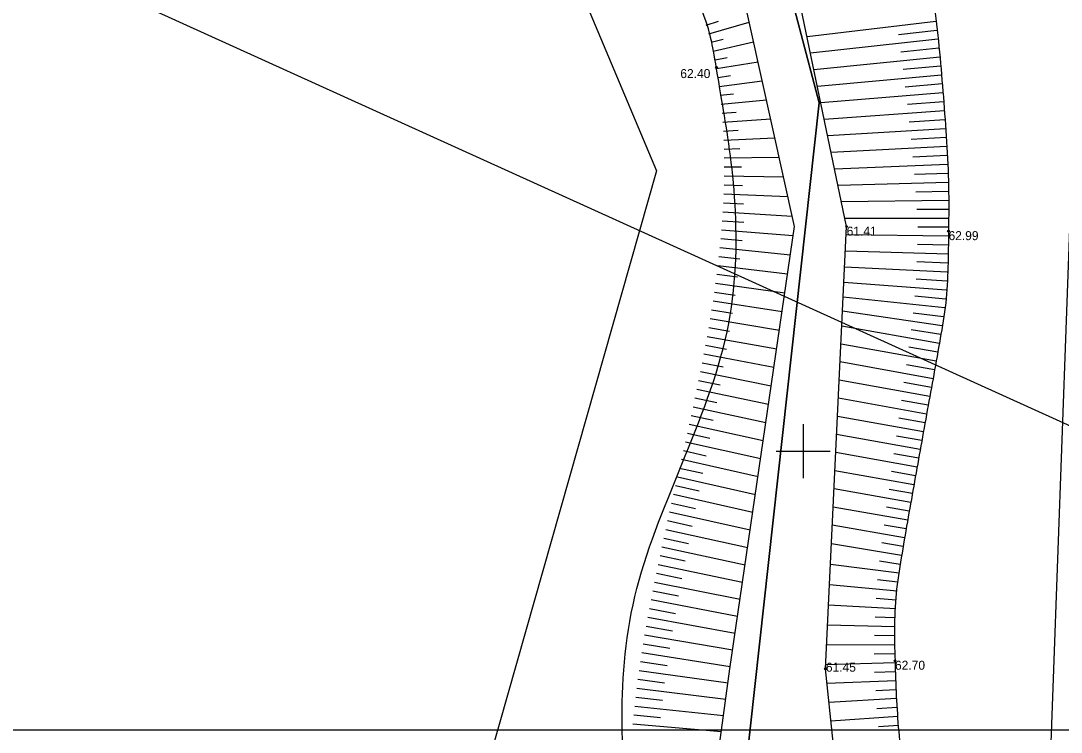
# Model space of a CAD drawing. Extents: x 616607 to 617499, y 408385 to 409695.
# Drawn here: x 617156.4 to 617214.4, y 409084.3 to 409124 of the extents above; entities that cross this region are included whole.
import ezdxf

# ---------------------------------------------------------------- set-up
doc = ezdxf.new("R2010")
doc.units = 0
for name, color, linetype in [('GEOD_ELEM_####_####_#', 7, 'Continuous'), ('HIDG_GRAV_####_####_#', 7, 'Continuous'), ('RAMI_PLAN_####_TKST_#', 7, 'Continuous'), ('RAMI_UZMR_####_####_#', 7, 'Continuous'), ('RELJ_AATZ_####_TKST_#', 7, 'Continuous'), ('RELJ_ELEM_####_####_#', 7, 'Continuous'), ('RELJ_NOGA_####_####_#', 7, 'Continuous'), ('ROBZ_IERR_####_####_#', 7, 'Continuous'), ('ROBZ_UZMR_####_####_#', 7, 'Continuous')]:
    doc.layers.add(name, color=color, linetype=linetype)

# ---------------------------------------------------------------- blocks, each defined once
blk = doc.blocks.new('PKT')
at = {"layer": 'RELJ_ELEM_####_####_#'}
blk.add_circle((0, 0), 0.05, dxfattribs=at)
blk = doc.blocks.new('KRUSTS')
at = {"layer": 'GEOD_ELEM_####_####_#'}
for p, q in [((0, 1.5), (0, 0)), ((-1.5, 0), (0, 0)), ((0, 0), (0, -1.5)), ((0, 0), (1.5, 0))]:
    blk.add_line(p, q, dxfattribs=at)

msp = doc.modelspace()

# ---------------------------------------------------------------- linework, layer by layer
at = {"layer": 'HIDG_GRAV_####_####_#'}
for points in [[(617196.049, 409072.553), (617193.886, 409072.979), (617195.921, 409087.874), (617195.921, 409087.874), (617199.518, 409112.516), (617194.569, 409134.842), (617162.019, 409207.474), (617151.93, 409229.107), (617149.428, 409241.28), (617152.359, 409253.938), (617188.564, 409303.055), (617197.968, 409312.659), (617223.456, 409346.169), (617232.567, 409363.51), (617247.671, 409422.509), (617276.576, 409461.456), (617285.007, 409472.526), (617327.765, 409527.3)], [(617198.671, 409072.074), (617200.929, 409072.435), (617202.532, 409075.622), (617201.237, 409087.874), (617202.422, 409112.516), (617197.415, 409136.544), (617162.613, 409207.758), (617153.021, 409229.447), (617150.525, 409241.262), (617153.298, 409253.658), (617189.431, 409302.264), (617198.754, 409312.12), (617224.478, 409345.652), (617234.105, 409363.027), (617250.009, 409421.44), (617285.914, 409471.848), (617328.6, 409526.531)]]:
    msp.add_lwpolyline(points, dxfattribs=at)
at = {"layer": 'RAMI_PLAN_####_TKST_#'}
msp.add_line((617156.405, 409127.944), (617287, 409068.676), dxfattribs=at)
msp.add_lwpolyline([(617109.674, 409084.461), (617109.674, 409290.339), (617251.246, 409290.339), (617251.246, 409084.461), (617109.674, 409084.461)], dxfattribs=at)
at = {"layer": 'RAMI_UZMR_####_####_#'}
msp.add_lwpolyline([(617101.571, 408748.246), (617213.472, 409074.039), (617215.883, 409140.56), (617165.121, 409241.478), (617252.137, 409353.424), (617269.572, 409425.099), (617332.631, 409510.312), (617439.945, 409622.037), (617425.373, 409635.959), (617242.079, 409440.82), (617216.614, 409355.716), (617136.613, 409246.751), (617191.828, 409115.62), (617145.545, 408952.8)], dxfattribs=at)
at = {"layer": 'RELJ_NOGA_####_####_#'}
for p, q in [((617194.588, 409123.746), (617195.272, 409123.966)), ((617194.588, 409123.746), (617194.588, 409123.746)), ((617194.734, 409123.268), (617196.991, 409123.918)), ((617207.391, 409123.949), (617200.219, 409123.088)), ((617207.391, 409123.949), (617207.392, 409123.949)), ((617194.734, 409123.268), (617194.733, 409123.268)), ((617207.45, 409123.452), (617205.309, 409123.207)), ((617207.45, 409123.452), (617207.45, 409123.452)), ((617194.866, 409122.786), (617195.54, 409122.958)), ((617194.866, 409122.786), (617194.866, 409122.786)), ((617194.984, 409122.3), (617197.235, 409122.813)), ((617207.506, 409122.955), (617200.409, 409122.173)), ((617207.506, 409122.955), (617207.507, 409122.956)), ((617194.984, 409122.3), (617194.983, 409122.3)), ((617195.088, 409121.811), (617195.77, 409121.943)), ((617207.61, 409121.961), (617200.6, 409121.257)), ((617207.559, 409122.458), (617205.442, 409122.239)), ((617207.559, 409122.458), (617207.559, 409122.458)), ((617207.61, 409121.961), (617207.611, 409121.961)), ((617195.088, 409121.811), (617195.088, 409121.811)), ((617195.176, 409121.319), (617197.483, 409121.696)), ((617207.658, 409121.463), (617205.57, 409121.264)), ((617207.658, 409121.463), (617207.659, 409121.463)), ((617195.176, 409121.319), (617195.175, 409121.319)), ((617195.253, 409120.825), (617195.957, 409120.928)), ((617195.253, 409120.825), (617195.253, 409120.825)), ((617207.705, 409120.965), (617200.794, 409120.329)), ((617207.705, 409120.965), (617207.706, 409120.966)), ((617195.322, 409120.33), (617195.321, 409120.329)), ((617195.322, 409120.33), (617197.716, 409120.643)), ((617207.748, 409120.467), (617205.69, 409120.29)), ((617207.748, 409120.467), (617207.749, 409120.467)), ((617195.383, 409119.833), (617196.119, 409119.917)), ((617195.383, 409119.833), (617195.383, 409119.833)), ((617195.437, 409119.336), (617197.95, 409119.59)), ((617207.79, 409119.969), (617200.983, 409119.421)), ((617207.79, 409119.969), (617207.791, 409119.969)), ((617195.437, 409119.336), (617195.436, 409119.336)), ((617207.829, 409119.471), (617205.804, 409119.317)), ((617207.829, 409119.471), (617207.83, 409119.471)), ((617195.482, 409118.838), (617196.258, 409118.902)), ((617195.482, 409118.838), (617195.482, 409118.838)), ((617195.52, 409118.34), (617198.188, 409118.516)), ((617207.866, 409118.972), (617201.177, 409118.489)), ((617207.901, 409118.473), (617205.914, 409118.335)), ((617207.866, 409118.972), (617207.867, 409118.972)), ((617207.901, 409118.473), (617207.902, 409118.473)), ((617195.52, 409118.34), (617195.519, 409118.34)), ((617195.551, 409117.841), (617196.377, 409117.885)), ((617207.934, 409117.974), (617201.369, 409117.569)), ((617207.934, 409117.974), (617207.935, 409117.974)), ((617195.551, 409117.841), (617195.551, 409117.841)), ((617195.575, 409117.341), (617195.574, 409117.341)), ((617195.575, 409117.341), (617198.422, 409117.459)), ((617207.964, 409117.475), (617206.015, 409117.362)), ((617207.964, 409117.475), (617207.964, 409117.475)), ((617195.591, 409116.841), (617196.476, 409116.865)), ((617195.591, 409116.841), (617195.591, 409116.841)), ((617207.992, 409116.976), (617201.561, 409116.646)), ((617207.992, 409116.976), (617207.993, 409116.976)), ((617195.601, 409116.342), (617195.6, 409116.342)), ((617195.601, 409116.342), (617198.66, 409116.384)), ((617208.016, 409116.477), (617206.109, 409116.385)), ((617208.016, 409116.477), (617208.017, 409116.477)), ((617195.603, 409115.842), (617195.603, 409115.842)), ((617195.603, 409115.842), (617196.556, 409115.842)), ((617208.038, 409115.977), (617201.755, 409115.714)), ((617208.038, 409115.977), (617208.039, 409115.977)), ((617195.6, 409115.342), (617195.599, 409115.342)), ((617195.6, 409115.342), (617198.901, 409115.297)), ((617208.073, 409114.978), (617201.945, 409114.802)), ((617208.057, 409115.477), (617206.194, 409115.415)), ((617208.057, 409115.477), (617208.057, 409115.477)), ((617208.073, 409114.978), (617208.074, 409114.978)), ((617195.59, 409114.842), (617195.589, 409114.842)), ((617195.59, 409114.842), (617196.62, 409114.813)), ((617208.085, 409114.478), (617206.271, 409114.44)), ((617208.085, 409114.478), (617208.085, 409114.478)), ((617195.552, 409113.842), (617195.551, 409113.842)), ((617195.552, 409113.842), (617196.665, 409113.787)), ((617195.574, 409114.342), (617195.573, 409114.342)), ((617195.574, 409114.342), (617199.144, 409114.203)), ((617208.094, 409113.978), (617202.134, 409113.895)), ((617208.094, 409113.978), (617208.095, 409113.978)), ((617195.524, 409113.343), (617195.523, 409113.343)), ((617195.524, 409113.343), (617199.386, 409113.108)), ((617208.1, 409113.478), (617206.339, 409113.463)), ((617208.1, 409113.478), (617208.1, 409113.478)), ((617195.491, 409112.844), (617195.49, 409112.844)), ((617195.491, 409112.844), (617196.696, 409112.757)), ((617208.101, 409112.978), (617202.326, 409112.973)), ((617208.101, 409112.978), (617208.102, 409112.978)), ((617195.452, 409112.346), (617195.451, 409112.346)), ((617195.452, 409112.346), (617199.445, 409112.016)), ((617208.094, 409111.978), (617202.4, 409112.063)), ((617208.099, 409112.478), (617206.395, 409112.494)), ((617208.099, 409112.478), (617208.1, 409112.478)), ((617195.408, 409111.848), (617195.408, 409111.848)), ((617195.408, 409111.848), (617196.596, 409111.739)), ((617208.084, 409111.478), (617206.372, 409111.516)), ((617208.084, 409111.478), (617208.085, 409111.478)), ((617208.094, 409111.978), (617208.095, 409111.978)), ((617195.36, 409111.35), (617195.359, 409111.35)), ((617195.36, 409111.35), (617199.288, 409110.943)), ((617208.071, 409110.978), (617202.356, 409111.151)), ((617208.071, 409110.978), (617208.072, 409110.978)), ((617195.249, 409110.356), (617195.248, 409110.356)), ((617195.249, 409110.356), (617199.133, 409109.882)), ((617195.306, 409110.853), (617195.306, 409110.853)), ((617195.306, 409110.853), (617196.478, 409110.721)), ((617208.054, 409110.479), (617206.338, 409110.552)), ((617208.054, 409110.479), (617208.054, 409110.479)), ((617195.186, 409109.86), (617195.186, 409109.86)), ((617195.186, 409109.86), (617196.348, 409109.711)), ((617208.031, 409109.979), (617202.313, 409110.255)), ((617208.031, 409109.979), (617208.032, 409109.979)), ((617195.12, 409109.365), (617195.119, 409109.365)), ((617195.12, 409109.365), (617198.98, 409108.834)), ((617207.967, 409108.981), (617202.272, 409109.41)), ((617208.002, 409109.48), (617206.29, 409109.591)), ((617208.002, 409109.48), (617208.003, 409109.48)), ((617195.05, 409108.87), (617195.05, 409108.87)), ((617195.05, 409108.87), (617196.206, 409108.7)), ((617207.875, 409107.985), (617202.233, 409108.589)), ((617207.925, 409108.483), (617206.223, 409108.636)), ((617207.967, 409108.981), (617207.968, 409108.981)), ((617194.976, 409108.375), (617194.975, 409108.375)), ((617194.976, 409108.375), (617198.827, 409107.786)), ((617207.925, 409108.483), (617207.926, 409108.483)), ((617194.899, 409107.881), (617194.898, 409107.881)), ((617194.899, 409107.881), (617196.054, 409107.697)), ((617207.749, 409106.993), (617202.196, 409107.814)), ((617207.817, 409107.489), (617206.136, 409107.701)), ((617207.817, 409107.489), (617207.817, 409107.489)), ((617207.875, 409107.985), (617207.876, 409107.985)), ((617194.734, 409106.895), (617194.733, 409106.895)), ((617194.734, 409106.895), (617195.893, 409106.693)), ((617194.818, 409107.388), (617194.817, 409107.388)), ((617194.818, 409107.388), (617198.675, 409106.74)), ((617207.587, 409106.007), (617202.155, 409106.967)), ((617207.749, 409106.993), (617207.75, 409106.993)), ((617194.647, 409106.402), (617194.646, 409106.403)), ((617194.647, 409106.402), (617198.524, 409105.707)), ((617207.672, 409106.499), (617206.024, 409106.772)), ((617207.672, 409106.499), (617207.673, 409106.499)), ((617194.557, 409105.911), (617194.557, 409105.911)), ((617194.557, 409105.911), (617195.724, 409105.695)), ((617207.411, 409105.022), (617202.107, 409105.975)), ((617207.499, 409105.515), (617205.889, 409105.802)), ((617207.587, 409106.007), (617207.588, 409106.007)), ((617194.465, 409105.419), (617194.464, 409105.419)), ((617194.465, 409105.419), (617198.373, 409104.676)), ((617207.499, 409105.515), (617207.499, 409105.514)), ((617194.37, 409104.928), (617194.37, 409104.928)), ((617194.37, 409104.928), (617195.548, 409104.698)), ((617207.234, 409104.038), (617202.059, 409104.974)), ((617207.323, 409104.53), (617205.751, 409104.815)), ((617207.323, 409104.53), (617207.323, 409104.53)), ((617207.411, 409105.022), (617207.412, 409105.022)), ((617194.174, 409103.948), (617194.174, 409103.948)), ((617194.174, 409103.948), (617195.366, 409103.703)), ((617194.273, 409104.438), (617194.272, 409104.438)), ((617194.273, 409104.438), (617198.223, 409103.647)), ((617207.055, 409103.054), (617202.011, 409103.969)), ((617207.234, 409104.038), (617207.235, 409104.038)), ((617194.073, 409103.458), (617194.072, 409103.458)), ((617194.073, 409103.458), (617198.075, 409102.63)), ((617207.145, 409103.546), (617205.612, 409103.824)), ((617207.145, 409103.546), (617207.145, 409103.546)), ((617193.97, 409102.969), (617193.97, 409102.969)), ((617193.97, 409102.969), (617195.179, 409102.713)), ((617206.877, 409102.07), (617201.962, 409102.962)), ((617206.966, 409102.562), (617205.472, 409102.833)), ((617207.055, 409103.054), (617207.056, 409103.054)), ((617193.866, 409102.48), (617193.865, 409102.48)), ((617193.866, 409102.48), (617197.925, 409101.607)), ((617206.966, 409102.562), (617206.966, 409102.562)), ((617193.761, 409101.991), (617193.76, 409101.991)), ((617193.761, 409101.991), (617194.988, 409101.725)), ((617206.699, 409101.086), (617201.913, 409101.943)), ((617206.788, 409101.578), (617205.333, 409101.841)), ((617206.877, 409102.07), (617206.878, 409102.07)), ((617193.654, 409101.502), (617193.653, 409101.503)), ((617193.654, 409101.502), (617197.778, 409100.596)), ((617206.699, 409101.086), (617206.7, 409101.086)), ((617206.788, 409101.578), (617206.788, 409101.578)), ((617193.437, 409100.526), (617193.436, 409100.526)), ((617193.437, 409100.526), (617197.631, 409099.588)), ((617193.546, 409101.014), (617193.546, 409101.014)), ((617193.546, 409101.014), (617194.793, 409100.737)), ((617206.523, 409100.102), (617201.865, 409100.932)), ((617206.611, 409100.594), (617205.194, 409100.848)), ((617206.611, 409100.594), (617206.611, 409100.594)), ((617193.328, 409100.038), (617193.328, 409100.038)), ((617193.328, 409100.038), (617194.597, 409099.752)), ((617206.348, 409099.117), (617201.816, 409099.924)), ((617206.523, 409100.102), (617206.524, 409100.102)), ((617193.218, 409099.55), (617193.217, 409099.551)), ((617193.218, 409099.55), (617197.485, 409098.589)), ((617206.435, 409099.61), (617205.057, 409099.855)), ((617206.435, 409099.61), (617206.436, 409099.61)), ((617193.108, 409099.063), (617193.108, 409099.063)), ((617193.108, 409099.063), (617194.399, 409098.77)), ((617206.173, 409098.133), (617201.768, 409098.915)), ((617206.26, 409098.625), (617204.92, 409098.863)), ((617206.348, 409099.117), (617206.349, 409099.117)), ((617192.998, 409098.575), (617192.997, 409098.575)), ((617192.998, 409098.575), (617197.339, 409097.592)), ((617206.26, 409098.625), (617206.26, 409098.625)), ((617192.777, 409097.6), (617192.776, 409097.6)), ((617192.777, 409097.6), (617197.195, 409096.602)), ((617192.887, 409098.087), (617192.887, 409098.087)), ((617192.887, 409098.087), (617194.201, 409097.79)), ((617205.998, 409097.148), (617201.719, 409097.904)), ((617206.085, 409097.64), (617204.783, 409097.871)), ((617206.085, 409097.64), (617206.086, 409097.64)), ((617206.173, 409098.133), (617206.174, 409098.133)), ((617192.667, 409097.112), (617192.667, 409097.112)), ((617192.667, 409097.112), (617194.004, 409096.812)), ((617205.998, 409097.148), (617205.999, 409097.148)), ((617192.557, 409096.624), (617192.556, 409096.624)), ((617192.557, 409096.624), (617197.051, 409095.616)), ((617205.825, 409096.163), (617201.67, 409096.889)), ((617205.912, 409096.656), (617204.647, 409096.878)), ((617205.912, 409096.656), (617205.912, 409096.656)), ((617192.448, 409096.136), (617192.448, 409096.136)), ((617192.448, 409096.136), (617193.808, 409095.834)), ((617205.654, 409095.178), (617201.622, 409095.876)), ((617205.739, 409095.671), (617204.511, 409095.884)), ((617205.825, 409096.163), (617205.826, 409096.163)), ((617192.34, 409095.648), (617192.339, 409095.648)), ((617192.34, 409095.648), (617196.908, 409094.638)), ((617205.739, 409095.671), (617205.74, 409095.671)), ((617192.127, 409094.671), (617192.126, 409094.671)), ((617192.127, 409094.671), (617196.767, 409093.674)), ((617192.233, 409095.16), (617192.233, 409095.16)), ((617192.233, 409095.16), (617193.614, 409094.857)), ((617205.485, 409094.192), (617201.572, 409094.846)), ((617205.569, 409094.685), (617204.377, 409094.889)), ((617205.569, 409094.685), (617205.569, 409094.685)), ((617205.654, 409095.178), (617205.655, 409095.178)), ((617192.022, 409094.182), (617192.022, 409094.182)), ((617192.022, 409094.182), (617193.425, 409093.885)), ((617205.485, 409094.192), (617205.486, 409094.192)), ((617191.919, 409093.693), (617191.918, 409093.693)), ((617191.919, 409093.693), (617196.626, 409092.708)), ((617205.34, 409093.203), (617201.517, 409093.692)), ((617205.408, 409093.698), (617204.249, 409093.868)), ((617205.408, 409093.698), (617205.408, 409093.698)), ((617191.817, 409093.203), (617191.817, 409093.203)), ((617191.817, 409093.203), (617193.239, 409092.911)), ((617205.34, 409093.203), (617205.341, 409093.203)), ((617191.717, 409092.713), (617191.716, 409092.714)), ((617191.717, 409092.713), (617196.487, 409091.754)), ((617205.23, 409092.209), (617201.462, 409092.559)), ((617205.281, 409092.707), (617204.143, 409092.834)), ((617205.281, 409092.707), (617205.281, 409092.706)), ((617191.619, 409092.223), (617191.619, 409092.223)), ((617191.619, 409092.223), (617193.059, 409091.939)), ((617205.189, 409091.711), (617204.063, 409091.797)), ((617205.23, 409092.209), (617205.231, 409092.209)), ((617191.43, 409091.241), (617191.43, 409091.241)), ((617191.43, 409091.241), (617192.885, 409090.968)), ((617191.524, 409091.732), (617191.523, 409091.732)), ((617191.524, 409091.732), (617196.348, 409090.803)), ((617205.156, 409091.212), (617201.408, 409091.43)), ((617205.156, 409091.212), (617205.157, 409091.212)), ((617205.189, 409091.711), (617205.189, 409091.711)), ((617191.339, 409090.749), (617191.338, 409090.75)), ((617191.339, 409090.749), (617196.211, 409089.861)), ((617205.131, 409090.713), (617204.006, 409090.76)), ((617205.131, 409090.713), (617205.131, 409090.713)), ((617191.251, 409090.257), (617191.251, 409090.257)), ((617191.251, 409090.257), (617192.719, 409089.998)), ((617205.113, 409090.213), (617201.354, 409090.306)), ((617205.113, 409090.213), (617205.114, 409090.213)), ((617191.166, 409089.765), (617191.165, 409089.765)), ((617191.166, 409089.765), (617196.075, 409088.928)), ((617205.104, 409089.713), (617203.971, 409089.728)), ((617205.104, 409089.713), (617205.104, 409089.713)), ((617191.084, 409089.271), (617191.084, 409089.271)), ((617191.084, 409089.271), (617192.561, 409089.029)), ((617205.102, 409089.213), (617201.3, 409089.19)), ((617205.102, 409089.213), (617205.103, 409089.213)), ((617190.93, 409088.283), (617190.929, 409088.283)), ((617190.93, 409088.283), (617192.414, 409088.062)), ((617191.005, 409088.778), (617191.004, 409088.778)), ((617191.005, 409088.778), (617195.94, 409088.005)), ((617205.107, 409088.713), (617203.957, 409088.695)), ((617205.107, 409088.713), (617205.107, 409088.713)), ((617190.858, 409087.788), (617190.857, 409087.789)), ((617190.858, 409087.788), (617195.814, 409087.091)), ((617205.119, 409088.213), (617201.248, 409088.099)), ((617205.136, 409087.713), (617203.976, 409087.669)), ((617205.119, 409088.213), (617205.12, 409088.213)), ((617205.136, 409087.713), (617205.136, 409087.713)), ((617190.79, 409087.293), (617190.79, 409087.293)), ((617190.79, 409087.293), (617192.278, 409087.096)), ((617205.156, 409087.214), (617201.324, 409087.05)), ((617205.156, 409087.214), (617205.157, 409087.214)), ((617190.726, 409086.797), (617190.725, 409086.797)), ((617190.726, 409086.797), (617195.69, 409086.188)), ((617205.18, 409086.714), (617204.04, 409086.657)), ((617205.18, 409086.714), (617205.18, 409086.714)), ((617190.666, 409086.301), (617190.666, 409086.301)), ((617190.666, 409086.301), (617192.154, 409086.125)), ((617205.206, 409086.215), (617201.435, 409086.002)), ((617205.206, 409086.215), (617205.207, 409086.215)), ((617190.611, 409085.804), (617190.61, 409085.804)), ((617190.611, 409085.804), (617195.565, 409085.27)), ((617205.236, 409085.716), (617204.112, 409085.647)), ((617205.236, 409085.716), (617205.236, 409085.716)), ((617190.515, 409084.809), (617190.514, 409084.809)), ((617190.515, 409084.809), (617195.444, 409084.38)), ((617190.56, 409085.306), (617190.56, 409085.306)), ((617190.56, 409085.306), (617192.044, 409085.163)), ((617205.268, 409085.217), (617201.545, 409084.964)), ((617205.268, 409085.217), (617205.269, 409085.217)), ((617205.302, 409084.718), (617204.191, 409084.639)), ((617205.302, 409084.718), (617205.302, 409084.718))]:
    msp.add_line(p, q, dxfattribs=at)
for points in [[(617336.806, 409523.735), (617334.087, 409521.174), (617331.368, 409518.613), (617328.65, 409516.053), (617321.193, 409509.03), (617314.57, 409501.094), (617308.568, 409492.793), (617305.546, 409488.614), (617302.537, 409484.426), (617299.516, 409480.247), (617296.49, 409476.063), (617293.469, 409471.875), (617290.436, 409467.695), (617287.772, 409464.025), (617284.965, 409460.461), (617282.252, 409456.826), (617279.55, 409453.205), (617276.887, 409449.558), (617274.256, 409445.882), (617271.624, 409442.206), (617269.17, 409438.414), (617266.782, 409434.573), (617265.581, 409432.642), (617264.455, 409430.674), (617263.346, 409428.69), (617262.228, 409426.69), (617261.169, 409424.668), (617260.166, 409422.606), (617258.56, 409419.302), (617257.132, 409415.931), (617255.903, 409412.47), (617254.682, 409409.035), (617253.531, 409405.585), (617252.579, 409402.073), (617251.627, 409398.563), (617250.683, 409395.052), (617249.746, 409391.538), (617248.81, 409388.023), (617247.876, 409384.508), (617246.956, 409380.989), (617246.456, 409379.078), (617246.028, 409377.149), (617245.649, 409375.21), (617245.269, 409373.268), (617244.984, 409371.31), (617244.622, 409369.366), (617244.259, 409367.42), (617243.878, 409365.48), (617243.456, 409363.545), (617243.245, 409362.576), (617242.967, 409361.625), (617242.691, 409360.672), (617242.413, 409359.713), (617242.093, 409358.772), (617241.734, 409357.838), (617241.092, 409356.173), (617240.315, 409354.578), (617239.389, 409353.048), (617238.465, 409351.519), (617237.498, 409350.034), (617236.402, 409348.636), (617235.3, 409347.23), (617234.195, 409345.828), (617233.083, 409344.431), (617231.973, 409343.038), (617230.863, 409341.647), (617229.743, 409340.262), (617227.764, 409337.815), (617225.693, 409335.438), (617223.461, 409333.217), (617221.215, 409330.983), (617218.873, 409328.856), (617216.607, 409326.646), (617214.346, 409324.442), (617212.093, 409322.231), (617209.875, 409319.98), (617208.771, 409318.86), (617207.791, 409317.635), (617206.772, 409316.432), (617205.753, 409315.229), (617204.825, 409314.017), (617203.96, 409312.646), (617203.768, 409312.342), (617203.633, 409312.004), (617203.62, 409311.655), (617203.607, 409311.284), (617203.603, 409310.913), (617203.599, 409310.542), (617203.595, 409310.167), (617203.603, 409309.793), (617203.596, 409309.419), (617203.588, 409309.066), (617203.48, 409308.714), (617203.309, 409308.4), (617202.615, 409307.13), (617201.9, 409305.914), (617201.16, 409304.689), (617200.419, 409303.462), (617199.689, 409302.232), (617198.921, 409301.021), (617197.385, 409298.6), (617195.744, 409296.251), (617194.012, 409293.966), (617188.331, 409286.47), (617182.548, 409279.072), (617176.617, 409271.78), (617175.091, 409269.904), (617173.565, 409268.03), (617172.006, 409266.181), (617170.46, 409264.348), (617168.875, 409262.548), (617167.326, 409260.717), (617165.749, 409258.854), (617164.19, 409256.978), (617162.652, 409255.082), (617161.86, 409254.106), (617161.109, 409253.1), (617160.341, 409252.105), (617159.552, 409251.081), (617158.796, 409250.055), (617158.061, 409248.97), (617157.091, 409247.54), (617156.549, 409245.874), (617156.301, 409244.175), (617156.178, 409243.327), (617156.153, 409242.478), (617156.175, 409241.631), (617156.198, 409240.798), (617156.24, 409239.966), (617156.347, 409239.134), (617156.709, 409236.311), (617157.141, 409233.481), (617158.294, 409230.866), (617161.329, 409223.986), (617164.552, 409217.339), (617167.894, 409210.677), (617170.758, 409204.966), (617173.578, 409199.236), (617176.506, 409193.56), (617179.423, 409187.907), (617182.384, 409182.277), (617185.301, 409176.624), (617188.243, 409170.922), (617191.171, 409165.213), (617194.071, 409159.489), (617195.541, 409156.585), (617196.952, 409153.652), (617198.382, 409150.727), (617199.832, 409147.761), (617201.227, 409144.774), (617202.61, 409141.772), (617203.681, 409139.449), (617204.533, 409137.047), (617205.282, 409134.589), (617206.022, 409132.164), (617206.554, 409129.71), (617206.943, 409127.212), (617207.329, 409124.726), (617207.611, 409122.242), (617207.809, 409119.738), (617208.005, 409117.248), (617208.126, 409114.753), (617208.097, 409112.263), (617208.074, 409110.266), (617207.983, 409108.256), (617207.635, 409106.282), (617207.283, 409104.281), (617206.913, 409102.294), (617206.558, 409100.3), (617206.203, 409098.306), (617205.85, 409096.331), (617205.506, 409094.315), (617205.165, 409092.324), (617205.06, 409090.322), (617205.116, 409088.325), (617205.171, 409086.355), (617205.316, 409084.384), (617205.484, 409082.414), (617205.653, 409080.435), (617205.914, 409078.469), (617206.09, 409076.495), (617206.126, 409076.085), (617206.005, 409075.66), (617206.103, 409075.26)], [(617191.5, 409068.875), (617191.187, 409071.639), (617190.873, 409074.403), (617190.56, 409077.167), (617188.889, 409091.892), (617197.619, 409106.66), (617195.165, 409121.386), (617194.844, 409123.312), (617194.157, 409125.135), (617193.325, 409126.9), (617187.756, 409138.717), (617181.857, 409150.154), (617176.29, 409161.887), (617165.241, 409185.172), (617154.985, 409208.835), (617144.902, 409232.447), (617143.246, 409236.327), (617146.946, 409242.229), (617143.832, 409245.09), (617142.81, 409246.028), (617141.789, 409246.966), (617140.768, 409247.904)]]:
    msp.add_open_spline(points, degree=3, dxfattribs=at)
at = {"layer": 'ROBZ_IERR_####_####_#'}
msp.add_lwpolyline([(617119.605, 409263.967), (617148.652, 409247.272), (617150.138, 409230.13), (617196.507, 409136.07), (617200.886, 409119.423), (617196.025, 409075.262), (617232.282, 409073.757)], dxfattribs=at)
at = {"layer": 'ROBZ_UZMR_####_####_#'}
msp.add_lwpolyline([(617232.583, 409073.745), (617196.025, 409075.262), (617200.886, 409119.423), (617196.507, 409136.07), (617150.138, 409230.13), (617148.652, 409247.272), (617201.229, 409318.934), (617233.453, 409357.938), (617244.928, 409391.934), (617250.98, 409414.497), (617255.789, 409432.426), (617326.39, 409521.291), (617332.188, 409529.592), (617332.358, 409529.835), (617335.391, 409534.333), (617341.051, 409533.641), (617349.913, 409536.856), (617370.73, 409556.7), (617378.749, 409547.935), (617381.343, 409545.1)], dxfattribs=at)

# ---------------------------------------------------------------- block references
at = {"layer": 'GEOD_ELEM_####_####_#'}
msp.add_blockref('KRUSTS', (617200, 409100), dxfattribs=at)
at = {"layer": 'RELJ_ELEM_####_####_#'}
for p in [(617195.165, 409121.386), (617202.422, 409112.516), (617208.097, 409112.263), (617205.116, 409088.325), (617201.237, 409087.874)]:
    msp.add_blockref('PKT', p, dxfattribs=at)

# ---------------------------------------------------------------- texts
at = {"layer": 'RELJ_AATZ_####_TKST_#'}
for s, p in [('62.40', (617193.154, 409120.794)), ('61.41', (617202.422, 409112.016)), ('62.99', (617208.097, 409111.763)), ('62.70', (617205.116, 409087.825)), ('61.45', (617201.263, 409087.716))]:
    msp.add_text(s, height=0.5, dxfattribs=at).set_placement(p)

doc.saveas('drawing.dxf')
